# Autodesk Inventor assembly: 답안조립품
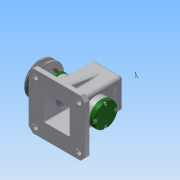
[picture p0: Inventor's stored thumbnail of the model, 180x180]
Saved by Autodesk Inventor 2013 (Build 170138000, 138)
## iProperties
Created: 2016-02
Part Number: 답안조립품
Document SubType Name: Assembly
Designer: Administrator
Author: Administrator
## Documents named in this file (16)
- C:\Users\Administrator\Desktop\460212V1021\답안조립품.iam
- C:\Users\Administrator\Desktop\460212V1021\답안도면.ipt
- C:\Users\Administrator\Desktop\460212V1021\V벨트풀리.ipt
- C:\Users\Administrator\Desktop\460212V1021\고정핀 1.2 x 10.ipt
- C:\Users\Administrator\Desktop\460212V1021\뒤커버.ipt
- C:\Users\Administrator\Desktop\460212V1021\링크.ipt
- C:\Users\Administrator\Desktop\460212V1021\멈춤나사 M3x8.ipt
- C:\Users\Administrator\Desktop\460212V1021\베어링 12 x 32 x 10.ipt
- C:\Users\Administrator\Desktop\460212V1021\볼트 M4 x 12.ipt
- C:\Users\Administrator\Desktop\460212V1021\부시.ipt
- C:\Users\Administrator\Desktop\460212V1021\슬라이드.ipt
- C:\Users\Administrator\Desktop\460212V1021\앞커버.ipt
- C:\Users\Administrator\Desktop\460212V1021\오일실 12 25 7.ipt
- C:\Users\Administrator\Desktop\460212V1021\키 4 x 4 x 10.ipt
- C:\Users\Administrator\Desktop\460212V1021\편심축.ipt
- C:\Users\Administrator\Desktop\460212V1021\핀 5 x 18.ipt
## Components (11 placed, 4 different names)
1. V벨트풀리:1
2. 고정핀 1.2 x 10:1
3. 핀 5 x 18:1
4. ISO 4762 M4 x 12:1
5. ISO 4762 M4 x 12:2
6. ISO 4762 M4 x 12:3
7. ISO 4762 M4 x 12:4
8. ISO 4762 M4 x 12:5
9. ISO 4762 M4 x 12:6
10. ISO 4762 M4 x 12:7
11. ISO 4762 M4 x 12:8
